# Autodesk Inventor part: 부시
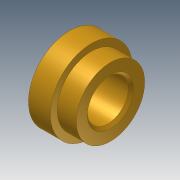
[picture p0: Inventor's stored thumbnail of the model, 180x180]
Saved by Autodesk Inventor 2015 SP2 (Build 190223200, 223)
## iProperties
Created: 2011-04
Part Number: 부시
Document SubType Name: Modeling
Designer: 한국산업디자인학원 [http://gmhk.co.kr]
Density: 1 g/cm^3
Material: 일반
Appearance: 황동 - 새틴
Mass: 7.35473 g
Surface Area: 30.152 cm^2
Volume: 7.35473 cm^3
Author: pww
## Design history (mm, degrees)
sketch "스케치1"
  geometry: L1 (0, 0)-(15, 0); L2 (0, 6)-(15, 6); L3 (15, 6)-(15, 12.5); L4 (15, 12.5)-(8, 12.5); L5 (8, 12.5)-(8, 15); L6 (8, 15)-(0, 15); L7 (0, 15)-(0, 6)
  constraints: 14 end point, 4 parallel, 2 vertical alignment, 1 horizontal, 1 perpendicular, 1 vertical
  dimensions: "d0" = 15 distance of L1.start L1.end; "d1" = 12 diameter of L2 L1; "d2" = 25 diameter of L4 L1; "d3" = 8 distance of L5.end L6.end; "d4" = 30 diameter of L6 L1
revolve "회전1" sketch "스케치1" stored, may be unused: angle "d5" = 90 deg
chamfer "모따기1" distance "d6" = 1; stored, may be unused: second distance "d7" = 2, angle "d8" = 45 deg
node "솔리드1"
